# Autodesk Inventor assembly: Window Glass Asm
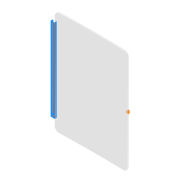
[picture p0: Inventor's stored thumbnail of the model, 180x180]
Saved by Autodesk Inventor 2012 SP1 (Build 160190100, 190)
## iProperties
Created: 2006-09
Part Number: Window Glass Asm
Document SubType Name: Assembly
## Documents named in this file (3)
- D:\Backup\CMU Work Temp\XX\Inv2012DynSim\Sub-Assemblies\Window Glass Asm.iam
- D:\Backup\CMU Work Temp\XX\Inv2012DynSim\Parts\Guide.ipt
- D:\Backup\CMU Work Temp\XX\Inv2012DynSim\Parts\Window Glass.ipt
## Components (2 placed, 2 different names)
1. Guide:1 — Mate:1, Mate:2
2. Window Glass:1 — Flush:1, Mate:1, Mate:2
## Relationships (3: Mate 2, Flush 1)
- Flush:1: Window Glass:1
- Mate:1: Guide:1 ↔ Window Glass:1
- Mate:2: Guide:1 ↔ Window Glass:1
